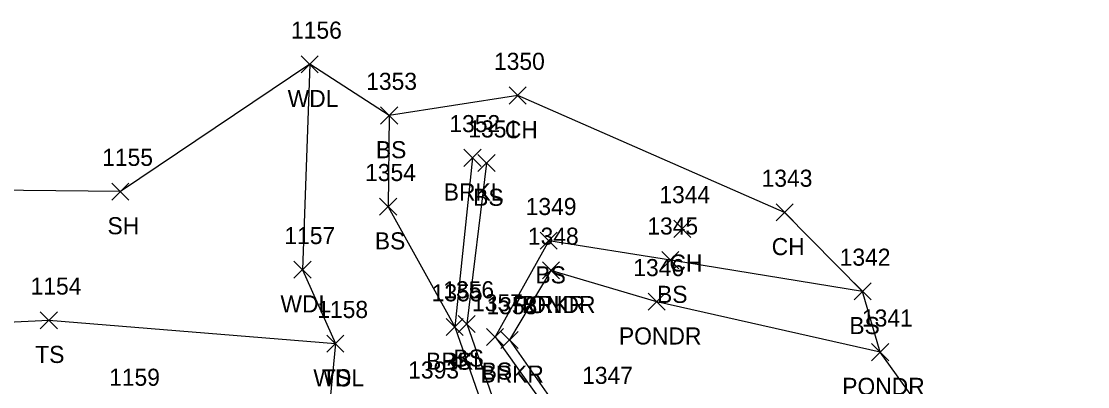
# Model space of a CAD drawing. Extents: x 1547013 to 1549434, y 267998 to 268739.
# Drawn here: x 1548542.6 to 1548667.4, y 268186.1 to 268228.8 of the extents above; entities that cross this region are included whole.
import ezdxf

# ---------------------------------------------------------------- set-up
doc = ezdxf.new("R2010")
doc.units = 0
for name, color, linetype in [('L_A', 7, 'Continuous'), ('L_I', 7, 'Continuous'), ('L_TIC', 7, 'Continuous'), ('LAWA', 7, 'Continuous'), ('LAWE', 7, 'Continuous'), ('LELB', 7, 'Continuous'), ('LSOGP', 7, 'Continuous'), ('U_I', 7, 'Continuous')]:
    doc.layers.add(name, color=color, linetype=linetype)

msp = doc.modelspace()

# ---------------------------------------------------------------- linework, layer by layer
at = {"layer": 'L_TIC'}
for points in [[(1548575.37, 268222.8), (1548577.37, 268224.8)], [(1548577.37, 268222.8), (1548575.37, 268224.8)], [(1548599.72, 268219.15), (1548601.72, 268221.15)], [(1548601.72, 268219.15), (1548599.72, 268221.15)], [(1548584.67, 268216.81), (1548586.67, 268218.81)], [(1548586.67, 268216.81), (1548584.67, 268218.81)], [(1548594.42, 268211.86), (1548596.42, 268213.86)], [(1548596.42, 268211.86), (1548594.42, 268213.86)], [(1548596.06, 268211.24), (1548598.06, 268213.24)], [(1548598.06, 268211.24), (1548596.06, 268213.24)], [(1548553.2, 268207.91), (1548555.2, 268209.91)], [(1548555.2, 268207.91), (1548553.2, 268209.91)], [(1548584.55, 268206.14), (1548586.55, 268208.14)], [(1548586.55, 268206.14), (1548584.55, 268208.14)], [(1548630.96, 268205.47), (1548632.96, 268207.47)], [(1548632.96, 268205.47), (1548630.96, 268207.47)], [(1548619, 268203.55), (1548621, 268205.55)], [(1548621, 268203.55), (1548619, 268205.55)], [(1548603.35, 268202.16), (1548605.35, 268204.16)], [(1548605.35, 268202.16), (1548603.35, 268204.16)], [(1548617.59, 268199.88), (1548619.59, 268201.88)], [(1548619.59, 268199.88), (1548617.59, 268201.88)], [(1548574.52, 268198.76), (1548576.52, 268200.76)], [(1548576.52, 268198.76), (1548574.52, 268200.76)], [(1548603.61, 268198.69), (1548605.61, 268200.69)], [(1548605.61, 268198.69), (1548603.61, 268200.69)], [(1548603.61, 268198.69), (1548605.61, 268200.69)], [(1548605.61, 268198.69), (1548603.61, 268200.69)], [(1548640.1, 268196.23), (1548642.1, 268198.23)], [(1548642.1, 268196.23), (1548640.1, 268198.23)], [(1548616, 268195.01), (1548618, 268197.01)], [(1548618, 268195.01), (1548616, 268197.01)], [(1548544.82, 268192.85), (1548546.82, 268194.85)], [(1548546.82, 268192.85), (1548544.82, 268194.85)], [(1548592.34, 268192.06), (1548594.34, 268194.06)], [(1548594.34, 268192.06), (1548592.34, 268194.06)], [(1548592.34, 268192.06), (1548594.34, 268194.06)], [(1548594.34, 268192.06), (1548592.34, 268194.06)], [(1548593.75, 268192.42), (1548595.75, 268194.42)], [(1548595.75, 268192.42), (1548593.75, 268194.42)], [(1548597.06, 268190.9), (1548599.06, 268192.9)], [(1548599.06, 268190.9), (1548597.06, 268192.9)], [(1548578.38, 268190.11), (1548580.38, 268192.11)], [(1548580.38, 268190.11), (1548578.38, 268192.11)], [(1548578.38, 268190.11), (1548580.38, 268192.11)], [(1548580.38, 268190.11), (1548578.38, 268192.11)], [(1548598.76, 268190.55), (1548600.76, 268192.55)], [(1548600.76, 268190.55), (1548598.76, 268192.55)], [(1548642.15, 268189.11), (1548644.15, 268191.11)], [(1548644.15, 268189.11), (1548642.15, 268191.11)]]:
    msp.add_lwpolyline(points, dxfattribs=at)
at = {"layer": 'LAWA'}
msp.add_lwpolyline([(1548576.37, 268223.8), (1548575.52, 268199.76), (1548579.38, 268191.11), (1548576.5, 268161.35)], dxfattribs=at)
at = {"layer": 'LAWE'}
for points in [[(1548595.42, 268212.86), (1548593.34, 268193.06), (1548599.1, 268176.6), (1548593.04, 268165.4)], [(1548604.61, 268199.69), (1548599.76, 268191.55), (1548607.13, 268181.04), (1548602.54, 268175.28), (1548611.68, 268166.33), (1548605.51, 268161.82), (1548601.1, 268157.99), (1548590.24, 268150.95), (1548583.51, 268147.65)], [(1548643.15, 268190.11), (1548617, 268196.01), (1548604.61, 268199.69)]]:
    msp.add_lwpolyline(points, dxfattribs=at)
at = {"layer": 'LELB'}
for points in [[(1548585.67, 268217.81), (1548585.55, 268207.14), (1548593.34, 268193.06)], [(1548597.06, 268212.24), (1548594.75, 268193.42), (1548600.65, 268176.54), (1548599.63, 268173.1), (1548594.96, 268163.44)], [(1548498.29, 268206.72), (1548519.16, 268192.59), (1548545.82, 268193.85), (1548579.38, 268191.11)], [(1548641.1, 268197.23), (1548618.59, 268200.88), (1548604.35, 268203.16), (1548598.06, 268191.9), (1548605.86, 268181.01), (1548602.06, 268176.36), (1548602.12, 268172.62), (1548609.23, 268166.61), (1548604.1, 268163.17), (1548598.76, 268160.79), (1548589.18, 268151.66), (1548583.12, 268148.93), (1548580.65, 268150.54), (1548584.43, 268152.24), (1548588.79, 268154.3), (1548594.96, 268163.44)]]:
    msp.add_lwpolyline(points, dxfattribs=at)
at = {"layer": 'LSOGP'}
msp.add_lwpolyline([(1548691.82, 268155.29), (1548664.24, 268170.51), (1548654.95, 268173.75), (1548643.15, 268190.11), (1548641.1, 268197.23), (1548631.96, 268206.47), (1548600.72, 268220.15), (1548585.67, 268217.81), (1548576.37, 268223.8), (1548554.2, 268208.91), (1548523.9, 268209.23), (1548498.29, 268206.72), (1548480.17, 268203.98), (1548463.54, 268201.58)], dxfattribs=at)

# ---------------------------------------------------------------- texts
at = {"layer": 'L_A'}
for s, p in [('WDL', (1548573.78, 268218.8)), ('CH', (1548599.21, 268215.15)), ('BS', (1548584.11, 268212.81)), ('BRKL', (1548592.06, 268207.86)), ('BS', (1548595.5, 268207.24)), ('SH', (1548552.69, 268203.91)), ('BS', (1548583.99, 268202.14)), ('CH', (1548630.45, 268201.47)), ('CH', (1548618.48, 268199.55)), ('BS', (1548602.79, 268198.16)), ('BS', (1548617.03, 268195.88)), ('WDL', (1548572.94, 268194.76)), ('PONDR', (1548600.17, 268194.69)), ('BRKR', (1548601.2, 268194.69)), ('BS', (1548639.54, 268192.23)), ('PONDR', (1548612.57, 268191.01)), ('TS', (1548544.23, 268188.85)), ('BS', (1548593.19, 268188.42)), ('BRKL', (1548589.99, 268188.06)), ('BS', (1548591.78, 268188.06)), ('WDL', (1548576.79, 268186.11)), ('TS', (1548577.79, 268186.11)), ('BRKR', (1548596.35, 268186.55)), ('BS', (1548596.5, 268186.9)), ('PONDR', (1548638.71, 268185.11))]:
    msp.add_text(s, height=2, dxfattribs=at).set_placement(p)
at = {"layer": 'L_I'}
for s, p in [('1156', (1548574.18, 268226.8)), ('1350', (1548597.94, 268223.15)), ('1353', (1548582.98, 268220.81)), ('1352', (1548592.72, 268215.86)), ('1351', (1548594.94, 268215.24)), ('1155', (1548552.07, 268211.91)), ('1354', (1548582.85, 268210.14)), ('1343', (1548629.27, 268209.47)), ('1344', (1548617.3, 268207.55)), ('1349', (1548601.65, 268206.16)), ('1345', (1548615.89, 268203.88)), ('1157', (1548573.4, 268202.76)), ('1348', (1548601.91, 268202.69)), ('1348', (1548601.91, 268202.69)), ('1342', (1548638.41, 268200.23)), ('1346', (1548614.25, 268199.01)), ('1154', (1548543.69, 268196.85)), ('1355', (1548590.65, 268196.06)), ('1355', (1548590.65, 268196.06)), ('1356', (1548592, 268196.42)), ('1357', (1548595.37, 268194.9)), ('1358', (1548597.06, 268194.55)), ('1158', (1548577.25, 268194.11)), ('1158', (1548577.25, 268194.11)), ('1341', (1548641.02, 268193.11)), ('1393', (1548587.9, 268187.03)), ('1347', (1548608.26, 268186.4))]:
    msp.add_text(s, height=2, dxfattribs=at).set_placement(p)
at = {"layer": 'U_I'}
msp.add_text('1159', height=2, dxfattribs=at).set_placement((1548552.88, 268186.18))

doc.saveas('drawing.dxf')
